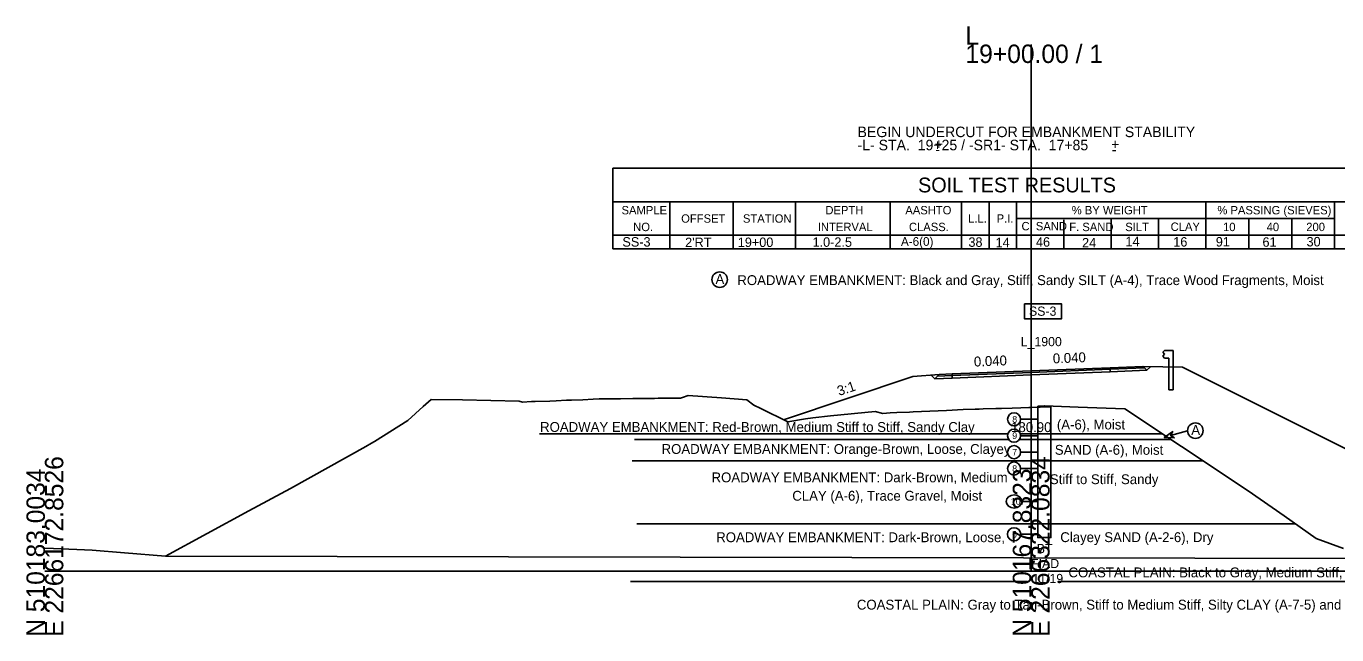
# Model space of a CAD drawing. Extents: x -827 to 2303, y -169 to 9934.
# Drawn here: x -2.8 to 196.5, y 7990.3 to 8082.9 of the extents above; entities that cross this region are included whole.
import ezdxf

# ---------------------------------------------------------------- set-up
doc = ezdxf.new("R2010")
doc.units = 0
for name, color, linetype in [('Default', 7, 'Continuous'), ('Exist Cross Section Cell', 7, 'Continuous'), ('Exist XS Center Line Elevation Label', 7, 'Continuous'), ('Exist XS Ground Line', 7, 'Continuous'), ('Geotech Sheets and Borders Cell', 7, 'Continuous'), ('Misc Plan Tools Cell', 7, 'Continuous'), ('Prop CMT Guardrail Graphics', 7, 'Continuous'), ('Prop CMT Pvmt Course 1', 7, 'Continuous'), ('Prop CMT Pvmt Course 2', 7, 'Continuous'), ('Prop CMT Pvmt Course 3', 7, 'Continuous'), ('Prop CMT Pvmt Surface', 7, 'Continuous'), ('Prop CMT Pvmt Surface Shoulder', 7, 'Continuous'), ('Prop CMT Shld Paved Course 1', 7, 'Continuous'), ('Prop CMT Shld Paved Course 2', 7, 'Continuous'), ('Prop CMT Shld Paved Course 3', 7, 'Continuous'), ('Prop CMT Slope Grass', 7, 'Continuous'), ('Prop CMT Subgrade Earthwork', 7, 'Continuous'), ('Prop DirtTable_ Soil Test Results - Tx (Sample Data)', 7, 'Continuous'), ('Prop Road Sect_ Boring - Header (Sample Box + Tx)', 7, 'Continuous'), ('Prop Road Sect_ Boring - Header Labels from Geopak', 7, 'Continuous'), ('Prop Road Sect_ Boring - Material (Outline)', 7, 'Continuous'), ('Prop Road Sect_ Boring - Peripheral (SPT Oval + Leader)', 7, 'Continuous'), ('Prop Road Sect_ Boring - Peripheral (SPT Tx)', 7, 'Continuous'), ('Prop Road Sect_ Material - Bubble + Leader + Bubble Tx', 7, 'Continuous'), ('Prop Road Sect_ Material - Contact (General - Major)', 7, 'Continuous'), ('Prop Road Sect_ Material - Contact (General - Minor)', 7, 'Continuous'), ('Prop Road Sect_ Material - Tx (Composite Desc)', 7, 'Continuous'), ('Prop Road Sect_ Recs - UC (Tx)', 7, 'Continuous'), ('Prop XS SE Text', 7, 'Continuous'), ('Prop XS Side Slope Text', 7, 'Continuous'), ('Scratch_Level_0', 7, 'Continuous')]:
    doc.layers.add(name, color=color, linetype=linetype)

msp = doc.modelspace()

# ---------------------------------------------------------------- linework, layer by layer
at = {"layer": 'Exist Cross Section Cell'}
for p, q in [((150, 8000), (150, 8080.11)), ((0, 8000), (150, 8000)), ((150, 8000), (300, 8000))]:
    msp.add_line(p, q, dxfattribs=at)
at = {"layer": 'Exist XS Ground Line'}
msp.add_lwpolyline([(0, 8003.47), (1.32, 8003.43), (7.21, 8003.19), (12.1, 8002.79), (18.35, 8002.26), (31.01, 8009.15), (37.37, 8012.57), (48.81, 8018.98), (49.65, 8019.45), (50.12, 8019.74), (55.2, 8022.89), (57.53, 8025.03), (58.75, 8026.09), (63.53, 8026.04), (72.11, 8025.87), (72.66, 8025.7), (73.99, 8025.78), (74.56, 8025.8), (76.79, 8025.87), (77.78, 8025.93), (79.32, 8026.01), (80.09, 8026.03), (81.82, 8026.07), (83.36, 8026.15), (84.3, 8026.19), (86.39, 8026.21), (86.81, 8026.21), (87.53, 8026.23), (89.43, 8026.27), (89.84, 8026.27), (90.98, 8026.27), (91.84, 8026.28), (92.29, 8026.28), (92.71, 8026.28), (93.28, 8026.29), (94.35, 8026.31), (95.41, 8026.31), (96.65, 8026.32), (96.96, 8026.42), (97.82, 8026.7), (102.92, 8026.35), (106.75, 8026.07), (107.81, 8025.25), (108.9, 8024.72), (113, 8022.7), (115.7, 8023.16), (116.81, 8023.34), (119.5, 8023.6), (126.25, 8024.29), (127.45, 8024), (128.53, 8024.06), (129.56, 8024.11), (131.52, 8024.2), (132.07, 8024.23), (134.58, 8024.35), (137.13, 8024.45), (139.67, 8024.58), (141.46, 8024.63), (142.1, 8024.65), (142.68, 8024.67), (144.62, 8024.74), (145.49, 8024.76), (147.12, 8024.79), (148.45, 8024.85), (149.63, 8024.9), (150.03, 8024.9), (151.32, 8024.92), (151.71, 8025.03), (152.1, 8025.15), (157.17, 8024.93), (164.23, 8024.68), (172.84, 8018.97), (182.99, 8012.2), (188.46, 8008.39), (193.34, 8004.95), (197.51, 8003.46)], dxfattribs=at)
at = {"layer": 'Geotech Sheets and Borders Cell'}
for p, q in [((86.37, 8061.3), (86.37, 8051.1)), ((86.37, 8061.3), (214.17, 8061.3)), ((86.37, 8056.2), (214.17, 8056.2)), ((95.05, 8056.2), (95.05, 8049.03)), ((104.66, 8056.2), (104.66, 8049.03)), ((114.18, 8056.2), (114.18, 8049.03)), ((128.55, 8056.2), (128.55, 8049.03)), ((139.4, 8056.2), (139.4, 8049.03)), ((143.6, 8056.2), (143.6, 8049.03)), ((147.79, 8056.2), (147.79, 8049.03)), ((176.57, 8056.23), (176.57, 8049.03)), ((196.14, 8056.2), (196.14, 8049.03)), ((147.79, 8053.65), (196.14, 8053.65)), ((154.99, 8053.45), (154.99, 8049.03)), ((162.18, 8053.65), (162.18, 8049.03)), ((169.37, 8049.03), (169.37, 8053.65)), ((183.09, 8053.65), (183.09, 8049.03)), ((189.62, 8053.65), (189.62, 8049.03)), ((86.37, 8051.1), (214.17, 8051.1)), ((86.37, 8051.1), (214.17, 8051.1)), ((86.37, 8051.1), (86.37, 8049.03)), ((86.37, 8049.03), (214.17, 8049.03)), ((86.37, 8049.03), (214.17, 8049.03))]:
    msp.add_line(p, q, dxfattribs=at)
at = {"layer": 'Misc Plan Tools Cell'}
msp.add_lwpolyline([(171.81, 8020.28), (170.23, 8020.35), (171.54, 8021.24), (171.19, 8020.62)], close=True, dxfattribs=at)
at = {"layer": 'Prop CMT Guardrail Graphics'}
for p, q in [((170.27, 8033.59), (170, 8033.3)), ((170, 8033.3), (170.27, 8033.01)), ((170.27, 8033.01), (170, 8032.72)), ((170, 8032.72), (170.27, 8032.42)), ((171.6, 8033.59), (170.27, 8033.59)), ((171.6, 8027.59), (171.6, 8033.59)), ((170.27, 8032.42), (170.94, 8032.42)), ((170.94, 8032.42), (170.94, 8027.59)), ((170.94, 8027.59), (171.6, 8027.59))]:
    msp.add_line(p, q, dxfattribs=at)
at = {"layer": 'Prop CMT Pvmt Course 1'}
for p, q in [((150, 8030.47), (162, 8030.95)), ((162, 8030.7), (150, 8030.22)), ((162, 8030.95), (162, 8030.7)), ((150, 8030.47), (138, 8029.99)), ((138, 8029.74), (150, 8030.22)), ((138, 8029.99), (138, 8029.74)), ((150, 8030.22), (150, 8030.47)), ((150, 8030.22), (150, 8030.47)), ((150, 8030.22), (150, 8030.35)), ((150, 8030.35), (150, 8030.35)), ((150, 8030.35), (150, 8030.22)), ((150, 8030.22), (150, 8030.35)), ((150, 8030.35), (150, 8030.35)), ((150, 8030.35), (150, 8030.22)), ((150, 8030.22), (150, 8030.22)), ((150, 8030.22), (150, 8030.22))]:
    msp.add_line(p, q, dxfattribs=at)
at = {"layer": 'Prop CMT Pvmt Course 2'}
for p, q in [((162, 8030.7), (150, 8030.22)), ((150, 8030.22), (162, 8030.7)), ((162, 8030.7), (162, 8030.7)), ((138, 8029.74), (150, 8030.22)), ((150, 8030.22), (138, 8029.74)), ((138, 8029.74), (138, 8029.74)), ((150, 8030.22), (150, 8030.22)), ((150, 8030.22), (150, 8030.22))]:
    msp.add_line(p, q, dxfattribs=at)
at = {"layer": 'Prop CMT Pvmt Course 3'}
for p, q in [((150, 8030.22), (162, 8030.7)), ((162, 8030.7), (162, 8030.32)), ((150, 8030.22), (138, 8029.74)), ((138, 8029.36), (150, 8029.84)), ((138, 8029.74), (138, 8029.36)), ((162, 8030.32), (150, 8029.84)), ((150, 8029.84), (150, 8030.22)), ((150, 8029.84), (150, 8030.22))]:
    msp.add_line(p, q, dxfattribs=at)
at = {"layer": 'Prop CMT Pvmt Surface'}
for q in [(162, 8030.95), (138, 8029.99)]:
    msp.add_line((150, 8030.47), q, dxfattribs=at)
at = {"layer": 'Prop CMT Pvmt Surface Shoulder'}
for p, q in [((162, 8030.95), (167, 8031.15)), ((138, 8029.99), (136, 8029.91))]:
    msp.add_line(p, q, dxfattribs=at)
at = {"layer": 'Prop CMT Shld Paved Course 1'}
for p, q in [((162, 8030.95), (167, 8031.15)), ((162, 8030.7), (162, 8030.95)), ((167.24, 8030.91), (162, 8030.7)), ((167, 8031.15), (167.24, 8030.91)), ((136, 8029.91), (135.74, 8029.65)), ((135.74, 8029.65), (138, 8029.74)), ((138, 8029.99), (136, 8029.91)), ((138, 8029.74), (138, 8029.99))]:
    msp.add_line(p, q, dxfattribs=at)
at = {"layer": 'Prop CMT Shld Paved Course 2'}
for p, q in [((162, 8030.7), (167.24, 8030.91)), ((167.24, 8030.91), (162, 8030.7)), ((162, 8030.7), (162, 8030.7)), ((167.24, 8030.91), (167.24, 8030.91)), ((138, 8029.74), (135.74, 8029.65)), ((135.74, 8029.65), (138, 8029.74)), ((135.74, 8029.65), (135.74, 8029.65)), ((138, 8029.74), (138, 8029.74))]:
    msp.add_line(p, q, dxfattribs=at)
at = {"layer": 'Prop CMT Shld Paved Course 3'}
for p, q in [((162, 8030.7), (167.24, 8030.91)), ((162, 8030.32), (162, 8030.7)), ((167.24, 8030.91), (167.24, 8030.91)), ((167.24, 8030.91), (167.6, 8030.55)), ((135.74, 8029.65), (135.35, 8029.26)), ((135.35, 8029.26), (138, 8029.36)), ((138, 8029.74), (135.74, 8029.65)), ((135.74, 8029.65), (135.74, 8029.65)), ((138, 8029.36), (138, 8029.74)), ((167.6, 8030.55), (162, 8030.32))]:
    msp.add_line(p, q, dxfattribs=at)
at = {"layer": 'Prop CMT Slope Grass'}
for p, q in [((167, 8031.15), (170, 8031.09)), ((170, 8031.09), (173, 8031.03)), ((173, 8031.03), (231, 8002.03)), ((132, 8029.59), (112.33, 8023.03)), ((136, 8029.91), (132, 8029.59))]:
    msp.add_line(p, q, dxfattribs=at)
at = {"layer": 'Prop CMT Subgrade Earthwork'}
for p, q in [((167.6, 8030.55), (168.18, 8031.13)), ((135.35, 8029.26), (134.79, 8029.81)), ((138, 8029.36), (135.35, 8029.26)), ((150, 8029.84), (138, 8029.36)), ((150, 8029.84), (162, 8030.32)), ((162, 8030.32), (167.6, 8030.55))]:
    msp.add_line(p, q, dxfattribs=at)
at = {"layer": 'Prop Road Sect_ Boring - Header (Sample Box + Tx)'}
msp.add_lwpolyline([(148.99, 8040.67), (154.59, 8040.67), (154.59, 8038.36), (148.99, 8038.36)], close=True, dxfattribs=at)
at = {"layer": 'Prop Road Sect_ Boring - Material (Outline)'}
for points in [[(151, 8025.1), (153, 8025.1), (153, 8025), (151, 8025)], [(151, 8025.1), (153, 8025.1), (153, 8025), (151, 8025)], [(151, 8025), (153, 8025), (153, 8020.9), (151, 8020.9)], [(151, 8025), (153, 8025), (153, 8020.9), (151, 8020.9)], [(151, 8020.9), (153, 8020.9), (153, 8020), (151, 8020)], [(151, 8020.9), (153, 8020.9), (153, 8020), (151, 8020)], [(151, 8020), (153, 8020), (153, 8016.8), (151, 8016.8)], [(151, 8020), (153, 8020), (153, 8016.8), (151, 8016.8)], [(151, 8016.8), (153, 8016.8), (153, 8007.2), (151, 8007.2)], [(151, 8016.8), (153, 8016.8), (153, 8007.2), (151, 8007.2)], [(151, 8007.2), (153, 8007.2), (153, 8005.1), (151, 8005.1)], [(151, 8007.2), (153, 8007.2), (153, 8005.1), (151, 8005.1)]]:
    msp.add_lwpolyline(points, close=True, dxfattribs=at)
at = {"layer": 'Prop Road Sect_ Boring - Peripheral (SPT Oval + Leader)'}
for p, q in [((151, 8023.1), (148.38, 8023.1)), ((151, 8020.6), (148.38, 8020.6)), ((151, 8018.1), (148.38, 8018.1)), ((151, 8015.6), (148.38, 8015.6)), ((151, 8010.6), (148.59, 8010.6)), ((151, 8005.6), (148.41, 8005.6))]:
    msp.add_line(p, q, dxfattribs=at)
for centre, major_axis, ratio in [((147.4, 8023.1), (0, 1), 0.983465), ((147.4, 8020.6), (0, 1), 0.983465), ((147.4, 8018.1), (0, 1), 0.983465), ((147.4, 8015.6), (0, 1), 0.983465), ((147.4, 8010.6), (1.19, 0), 0.841617), ((147.4, 8005.6), (1.01, 0), 0.992963)]:
    msp.add_ellipse(centre, major_axis=major_axis, ratio=ratio, dxfattribs=at)
at = {"layer": 'Prop Road Sect_ Material - Bubble + Leader + Bubble Tx'}
msp.add_line((173.8, 8021.36), (171.19, 8020.62), dxfattribs=at)
for centre in [(102.63, 8044.35), (174.97, 8021.37)]:
    msp.add_circle(centre, 1.18, dxfattribs=at)
at = {"layer": 'Prop Road Sect_ Material - Contact (General - Major)'}
msp.add_line((18.35, 8002.26), (201.71, 8001.93), dxfattribs=at)
at = {"layer": 'Prop Road Sect_ Material - Contact (General - Minor)'}
for p, q in [((146.46, 8020.9), (75.24, 8020.9)), ((151, 8020.9), (148.34, 8020.9)), ((153, 8020.9), (169.92, 8020.9)), ((146.61, 8020), (89.66, 8020)), ((151, 8020), (148.19, 8020)), ((153, 8020), (171.28, 8020)), ((151, 8016.8), (89.33, 8016.8)), ((153, 8016.8), (176.09, 8016.8)), ((151, 8007.2), (90.05, 8007.2)), ((153, 8007.2), (190.15, 8007.2)), ((149.39, 7998.4), (89.06, 7998.4)), ((268.06, 7998.4), (154.08, 7998.4))]:
    msp.add_line(p, q, dxfattribs=at)

# ---------------------------------------------------------------- texts
at = {"layer": 'Default'}
msp.add_text('-', height=0.0001, dxfattribs=at).set_placement((0, 8000))
msp.add_text('-', height=0.0001, dxfattribs=at).set_placement((0, 8000))
at = {"layer": 'Exist Cross Section Cell'}
for s, p in [('L', (140, 8080.11)), ('19+00.00 / 1', (140, 8077.31))]:
    msp.add_text(s, height=2.8, dxfattribs=at).set_placement(p)
for s, p in [('E 2266172.8526', (2.8, 7990)), ('E 2266322.0834', (152.8, 7990)), ('N 510183.0034', (0, 7990)), ('N 510167.8323', (150, 7990))]:
    msp.add_text(s, height=2.8, rotation=90, dxfattribs=at).set_placement(p)
at = {"layer": 'Exist XS Center Line Elevation Label'}
msp.add_text('180.90', height=1.5, dxfattribs=at).set_placement((146.95, 8021.15))
at = {"layer": 'Geotech Sheets and Borders Cell'}
for s, height, p in [('SOIL TEST RESULTS', 2.25, (132.8, 8057.62)), ('SAMPLE', 1.275, (87.7, 8054.28)), ('DEPTH', 1.275, (118.7, 8054.28)), ('AASHTO', 1.275, (130.86, 8054.28)), ('% BY WEIGHT', 1.275, (156.17, 8054.28)), ('% PASSING (SIEVES)', 1.275, (178.32, 8054.28)), ('NO.', 1.275, (89.47, 8051.73)), ('OFFSET', 1.275, (96.77, 8053.01)), ('STATION', 1.275, (106.16, 8053.01)), ('INTERVAL', 1.275, (117.55, 8051.73)), ('CLASS.', 1.275, (131.41, 8051.73)), ('L.L.', 1.275, (140.42, 8053.01)), ('P.I.', 1.275, (144.75, 8053.01)), ('C. SAND', 1.275, (148.53, 8051.85)), ('F. SAND', 1.275, (155.79, 8051.73)), ('SILT', 1.275, (164.31, 8051.73)), ('CLAY', 1.275, (171.21, 8051.76)), ('10', 1.275, (179.18, 8051.73)), ('40', 1.275, (185.81, 8051.73)), ('200', 1.275, (191.84, 8051.73))]:
    msp.add_text(s, height=height, dxfattribs=at).set_placement(p)
at = {"layer": 'Prop DirtTable_ Soil Test Results - Tx (Sample Data)'}
for s, height, p in [('SS-3', 1.44, (87.83, 8049.37)), ("2'RT", 1.44, (97.37, 8049.3)), ('19+00', 1.44, (105.38, 8049.31)), ('1.0-2.5', 1.44, (116.75, 8049.34)), ('A-6(0)', 1.327, (130.2, 8049.49)), ('38', 1.44, (140.46, 8049.34)), ('14', 1.44, (144.58, 8049.27)), ('46', 1.44, (150.73, 8049.36)), ('24', 1.44, (157.74, 8049.24)), ('14', 1.44, (164.34, 8049.43)), ('16', 1.44, (171.61, 8049.38)), ('91', 1.44, (178.08, 8049.39)), ('61', 1.44, (185.18, 8049.35)), ('30', 1.44, (191.88, 8049.4))]:
    msp.add_text(s, height=height, dxfattribs=at).set_placement(p)
at = {"layer": 'Prop Road Sect_ Boring - Header (Sample Box + Tx)'}
msp.add_text('SS-3', height=1.4, dxfattribs=at).set_placement((149.67, 8038.85))
at = {"layer": 'Prop Road Sect_ Boring - Header Labels from Geopak'}
for s, p in [('L_1900', (148.41, 8034.22)), ('BT', (150.85, 8002.72)), ('FIAD', (149.99, 8000.45)), ('11/19', (150.18, 7998.17))]:
    msp.add_text(s, height=1.4, dxfattribs=at).set_placement(p)
at = {"layer": 'Prop Road Sect_ Boring - Peripheral (SPT Tx)'}
for s, p in [('8', (147.12, 8022.6)), ('9', (147.12, 8020.1)), ('7', (147.12, 8017.6)), ('8', (147.12, 8015.1)), ('10', (146.91, 8010.1)), ('6', (147.09, 8005.1))]:
    msp.add_text(s, height=1, dxfattribs=at).set_placement(p)
at = {"layer": 'Prop Road Sect_ Material - Tx (Composite Desc)'}
for s, p in [('A', (101.99, 8043.68)), ('ROADWAY EMBANKMENT: Black and Gray, Stiff, Sandy SILT (A-4), Trace Wood Fragments, Moist', (105.31, 8043.52)), ('ROADWAY EMBANKMENT: Red-Brown, Medium Stiff to Stiff, Sandy Clay ', (75.31, 8021.18)), ('(A-6), Moist', (153.91, 8021.55)), ('A', (174.35, 8020.73)), ('ROADWAY EMBANKMENT: Orange-Brown, Loose, Clayey ', (93.79, 8017.83)), ('SAND (A-6), Moist', (153.6, 8017.7)), ('ROADWAY EMBANKMENT: Dark-Brown, Medium', (101.39, 8013.51)), (' Stiff to Stiff, Sandy ', (152.29, 8013.23)), ('CLAY (A-6), Trace Gravel, Moist', (113.67, 8010.71)), ('ROADWAY EMBANKMENT: Dark-Brown, Loose, ', (102.1, 8004.4)), (' Clayey SAND (A-2-6), Dry', (153.87, 8004.41)), ('COASTAL PLAIN: Black to Gray, Medium Stiff, Sandy SILT (A-4), Moist (Black Creek Formation)', (155.67, 7999.05)), ('COASTAL PLAIN: Gray to Tan-Brown, Stiff to Medium Stiff, Silty CLAY (A-7-5) and Sandy CLAY (A-6), Moist to Wet (Black Creek Formation)', (123.49, 7994.14))]:
    msp.add_text(s, height=1.5, dxfattribs=at).set_placement(p)
at = {"layer": 'Prop Road Sect_ Recs - UC (Tx)'}
for s, p in [('BEGIN UNDERCUT FOR EMBANKMENT STABILITY', (123.59, 8066.03)), ('-L- STA.  19+25 / -SR1- STA.  17+85', (123.59, 8064.03)), ('+', (135.33, 8064.18)), ('+', (162.17, 8064.15)), ('-', (135.44, 8063.37)), ('-', (162.27, 8063.35))]:
    msp.add_text(s, height=1.6, dxfattribs=at).set_placement(p)
at = {"layer": 'Prop XS SE Text'}
for p in [(141.32, 8031.12), (153.32, 8031.6)]:
    msp.add_text('0.040', height=1.5, rotation=2.2906, dxfattribs=at).set_placement(p)
at = {"layer": 'Prop XS Side Slope Text'}
msp.add_text('3:1', height=1.5, rotation=18.4332, dxfattribs=at).set_placement((120.79, 8026.64))
at = {"layer": 'Scratch_Level_0'}
for s, p in [('RT_GR_Graphics Out 08', (169.81, 8032.71)), ('RT_GR_Graphics Out 01', (169.81, 8033.29)), ('RT_GR_Graphics Out 02', (170.08, 8033.58)), ('RT_GR_Graphics Out 09', (170.08, 8033)), ('RT_GR_Graphics Out 03', (171.41, 8033.58)), ('RT_PV3_OEOT', (161.9, 8030.69)), ('RT_PV2_OEOT', (161.9, 8030.69)), ('RT_PV1_OEOT', (161.91, 8030.94)), ('RT_PS1_OEOP', (166.91, 8031.14)), ('RT_PS3_Shelf_Out', (167.1, 8030.9)), ('RT_PS3_OEOP', (167.14, 8030.9)), ('RT_PS2_OEOP', (167.14, 8030.9)), ('RT_Sub_Trench_Out_DLT', (167.98, 8031.12)), ('RT_GS_OS_GR_Face_Graphics', (169.77, 8031.08)), ('RT_GR_Graphics Out 07', (170.08, 8032.41)), ('RT_GR_Graphics Out 06', (170.75, 8032.41)), ('RT_GS_OS_CTL', (172.89, 8031.02)), ('LT_GS_OS_CTL', (131.89, 8029.58)), ('LT_Sub_Trench_Out_DLT', (134.6, 8029.8)), ('LT_Sub_Trench_Out', (135.19, 8029.25)), ('LT_PS3_Shelf_Out', (135.6, 8029.64)), ('LT_PS3_OEOP', (135.64, 8029.64)), ('LT_PS2_OEOP', (135.64, 8029.64)), ('LT_PS1_OEOP', (135.91, 8029.9)), ('LT_PV3_OEOT', (137.9, 8029.73)), ('LT_PV2_OEOT', (137.9, 8029.73)), ('LT_Sub_OEOT', (137.9, 8029.35)), ('LT_PV1_OEOT', (137.91, 8029.98)), ('RT_PV2_OEEOP', (149.89, 8030.21)), ('RT_PV3_OEEOP', (149.89, 8030.21)), ('LT_Sub_OEEOP', (149.89, 8029.83)), ('RT_Sub_OEEOP', (149.89, 8029.83)), ('RT_PV1_OEEOP', (149.9, 8030.34)), ('LT_PV1_OEEOP', (149.9, 8030.34)), ('RT_PV2_IEEOP', (149.9, 8030.21)), ('LT_PV2_IEEOP', (149.9, 8030.21)), ('LT_PV2_OEEOP', (149.89, 8030.21)), ('LT_PV3_OEEOP', (149.89, 8030.21)), ('RT_PV1_IEEOP', (149.9, 8030.34)), ('LT_PV1_IEEOP', (149.91, 8030.34)), ('PV2_PGL', (149.94, 8030.21)), ('PV1_PGL', (149.94, 8030.46)), ('RT_Sub_OEOT', (161.9, 8030.31)), ('RT_Sub_Trench_Out', (167.44, 8030.54)), ('RT_GR_Graphics Out 05', (170.75, 8027.58)), ('RT_GR_Graphics Out 04', (171.41, 8027.58)), ('LT_Slope_Fill', (112.23, 8023.02))]:
    msp.add_text(s, height=0.02, dxfattribs=at).set_placement(p)

doc.saveas('drawing.dxf')
